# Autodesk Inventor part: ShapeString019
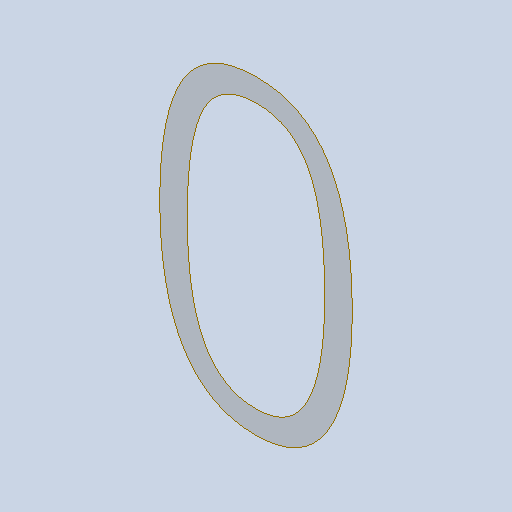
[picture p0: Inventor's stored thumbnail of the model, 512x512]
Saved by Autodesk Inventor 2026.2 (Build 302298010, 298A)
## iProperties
Created: 2026-10
Part Number: ShapeString019
Material: Générique
Document SubType Name: Modeling
Designer: mel
Density: 1 g/cm^3
Appearance: Par défaut
Author: mel
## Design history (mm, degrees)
feature "Composite1"
body "Srf1"
